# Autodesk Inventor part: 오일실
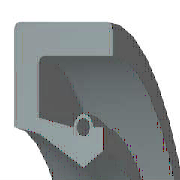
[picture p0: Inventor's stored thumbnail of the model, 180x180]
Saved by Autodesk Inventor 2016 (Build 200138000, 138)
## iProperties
Created: 2015-10
Part Number: 오일실
Material: 고무
Description: 오일-실
Document SubType Name: Modeling
Standard: KS B 2804
Designer: mdu
Standards Organization: KS
Language: ko-KR
Size Designation: S - 25 38 8
Categories: <MemberInstance><Categories><Category DisplayName="샤프트 부품" InternalName="7f7aeb1f-a693-4053-b835-cee3144e0d98" Mnemonic="SHFT"><Category DisplayName="실링" Intern
Density: 0.93 g/cm^3
Appearance: 고무 - 검은색 - 버전 1.1
Mass: 2.23721 g
Surface Area: 37.0166 cm^2
Volume: 2.4056 cm^3
IsCustomPart: 1
Author: mdu
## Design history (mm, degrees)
revolve "본체" stored, may be unused: angle "d17" = 90 deg
revolve "스프링1" stored, may be unused: angle "d18" = 90 deg
body "Solid1"
sketch "스케치1"
  geometry: L1 (0, 19)-(8, 19); L2 (8, 19)-(8, 17.75); L3 (8, 17.75)-(1.75, 17.75); L4 (0, 19)-(0, 14.6); L5 (0, 14.6)-(1.75, 14.25); L6 (1.75, 14.25)-(4.9, 12.5); L7 (4.9, 12.5)-(0, 12.5); L8 (6.3, 13.375)-(6.3, 14.6); L9 (0, 0)-(9.586, 0) reference; L10 (4.9, 12.5)-(6.3, 13.375); L11 (0, 18)-(0, -3) reference; L12 (-1.917, 0)-(11.503, 0) reference; L13 (4.2, 14.6)-(1.75, 15.09); L14 (1.75, 15.09)-(1.75, 17.75); L15 (6.3, 14.6)-(5.6, 14.6); C1 r 0.455 at (4.9, 14.6); A1 r 0.7 centre (4.9, 14.6) between (5.6, 14.6) and (4.2, 14.6)
  constraints: 26 end point, 5 horizontal alignment, 4 perpendicular, 2 centre point, 2 collinear, 2 horizontal, 2 parallel, 2 point on circle, 2 point on line, 2 vertical alignment, 1 coincident
  dimensions: "d0" = 38 diameter of L1 L9 (= SD2); "d1" = 26.75 diameter of L8.start L9 (= ABDM); "d2" = 1.25 distance of L1.end L2.end (computed from SD); "d3" = 0.91 diameter of C1 (= SPDI); "d4" = 1.4 diameter of A1 (= SPDA); "d5" = 25 diameter of L6.end L9 (= NND); "d6" = 28.5 diameter of L5.end L9 (= TKDM); "d7" = 29.2 diameter of L4.end L9 (= HLDM); "d8" = 4.9 distance from line of C1.centre L4 (= SPDST); "d9" = 6.3 distance between parallel lines of L8 L4 (= SDI); "d10" = 8 distance between parallel lines of L2 L4 (= SWDT); "d12" = 1.75 distance between parallel lines of L14 L4 (= SD)
fillet "모깎기1" dims "d11" = 0.3 (= RR)
other parameters: "SD2" = 38 [user parameter; used in 1 equation term], "SWDT" = 8 [user parameter; used in 1 equation term], "RR" = 0.3 [user parameter; used in 1 equation term], "SD" = 1.75 [user parameter; used in 2 equation terms], "NND" = 25 [user parameter; used in 1 equation term], "SPDA" = 1.4 [user parameter; used in 1 equation term], "SPDI" = 0.91 [user parameter; used in 1 equation term], "TKDM" = 28.5 [user parameter; used in 1 equation term], "HLDM" = 29.2 [user parameter; used in 1 equation term], "ABDM" = 26.75 [user parameter; used in 1 equation term], "SDI" = 6.3 [user parameter; used in 1 equation term], "SPDST" = 4.9 [user parameter; used in 1 equation term], "d13" = 0, "d14" = 0, "d15" = 0, "LAB" = 0.35 [user parameter]
